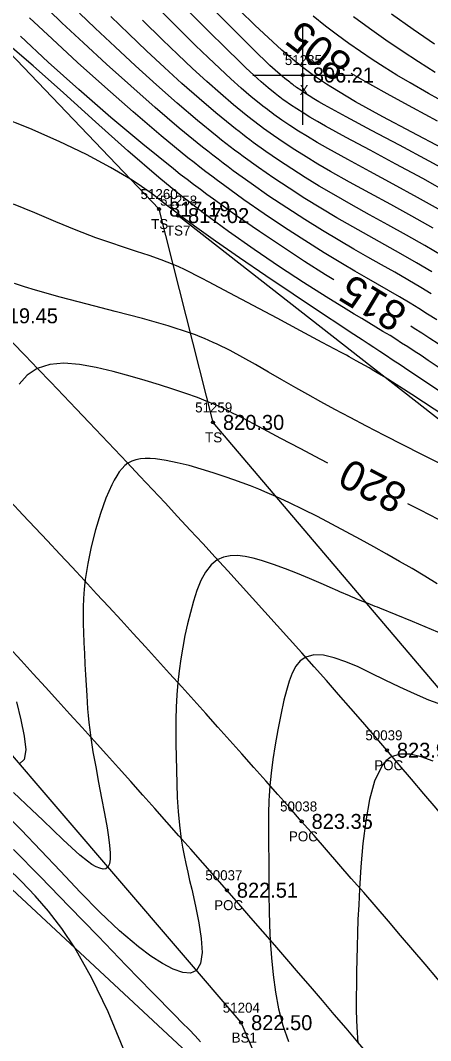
# Model space of a CAD drawing. Extents: x 1378535 to 1380697, y 997729 to 1000024.
# Drawn here: x 1380282.6 to 1380323.7, y 998356.1 to 998458.3 of the extents above; entities that cross this region are included whole.
import ezdxf

# ---------------------------------------------------------------- set-up
doc = ezdxf.new("R2010")
doc.units = 0
for name, color, linetype in [('RD_DTM_BkLn1', 7, 'Continuous'), ('RD_DTM_BkLn2', 7, 'Continuous'), ('RD_DTM_BkLn_txCode', 7, 'Continuous'), ('RD_DTM_Major1', 7, 'Continuous'), ('RD_DTM_Major1_Lbl', 7, 'Continuous'), ('RD_DTM_Minor1', 7, 'Continuous'), ('RD_EX_Misc', 7, 'Continuous'), ('RD_EX_Misc_txCode', 7, 'Continuous'), ('RD_EX_Road', 7, 'Continuous'), ('RD_EX_Road_txCode', 7, 'Continuous'), ('RD_EX_TX_Misc_ELEV', 7, 'Continuous'), ('RD_EX_TX_Road_ELEV', 7, 'Continuous'), ('RD_HC_Survey_ELEV', 7, 'Continuous'), ('RD_HC_Survey_txCode', 7, 'Continuous'), ('RD_SMD_Locator', 7, 'Continuous')]:
    doc.layers.add(name, color=color, linetype=linetype)

msp = doc.modelspace()

# ---------------------------------------------------------------- linework, layer by layer
at = {"layer": 'RD_DTM_BkLn1'}
msp.add_spline([(1380561.34, 997899.22), (1380543.7, 997960.78), (1380525.01, 998016.6), (1380501.32, 998075.31), (1380476.75, 998129.12), (1380448.82, 998181.2), (1380418.35, 998233.12), (1380383.22, 998285.15), (1380349.47, 998331.42), (1380310.82, 998378.03), (1380271.62, 998420.47), (1380231.53, 998459.85)], degree=3, dxfattribs=at)
at = {"layer": 'RD_DTM_BkLn2'}
for p, q in [((1380341.21, 998405.27), (1380298.43, 998438.72)), ((1380300.33, 998353.98), (1380252.92, 998398.07))]:
    msp.add_line(p, q, dxfattribs=at)
for points in [[(1380321.82, 998326.62), (1380322.66, 998329.17), (1380322.26, 998332.77), (1380321.14, 998334.34), (1380320.11, 998334.64), (1380319.18, 998334.52), (1380315.04, 998338.98), (1380309.47, 998346.95), (1380304.76, 998357.87), (1380262.27, 998407.43), (1380207.07, 998458.85), (1380160.07, 998502.83), (1380114.55, 998544.04), (1380071.67, 998582.11), (1380029.13, 998620.78), (1379985.01, 998662.48), (1379936.38, 998704.35), (1379893.88, 998744.8), (1379846.87, 998787.95), (1379800.33, 998830.07), (1379753.88, 998865.5), (1379725.58, 998874.5)], [(1380445.27, 998223.72), (1380425.52, 998250), (1380406.53, 998278.61), (1380381.95, 998317.02), (1380359.79, 998349.51), (1380336.16, 998377.73), (1380301.94, 998418), (1380296.54, 998439.37), (1380254.32, 998483.53), (1380245.59, 998494.96), (1380223.31, 998517.04), (1380192.01, 998537.14)]]:
    msp.add_lwpolyline(points, dxfattribs=at)
at = {"layer": 'RD_DTM_Major1'}
for points in [[(1380324, 998437.47), (1380321.88, 998438.65), (1380319.75, 998439.82), (1380317.65, 998440.97), (1380315.63, 998442.08), (1380313.73, 998443.14), (1380312.46, 998443.88), (1380311.27, 998444.6), (1380310.14, 998445.31), (1380309.06, 998446.02), (1380308.01, 998446.73), (1380307, 998447.45), (1380306.71, 998447.67), (1380306.43, 998447.88), (1380306.14, 998448.1), (1380305.85, 998448.32), (1380305.56, 998448.55), (1380305.27, 998448.78), (1380304.01, 998449.81), (1380302.69, 998450.94), (1380301.32, 998452.15), (1380299.89, 998453.46), (1380298.41, 998454.85), (1380296.87, 998456.33), (1380294.86, 998458.29)], [(1380314.05, 998432.29), (1380313.21, 998432.8), (1380311.11, 998434.13), (1380308.9, 998435.58), (1380306.61, 998437.11), (1380304.29, 998438.71), (1380301.98, 998440.36), (1380301.32, 998440.84), (1380300.67, 998441.33), (1380300, 998441.82), (1380299.34, 998442.33), (1380298.66, 998442.85), (1380297.98, 998443.39), (1380294.91, 998445.86), (1380291.71, 998448.56), (1380288.5, 998451.35), (1380285.43, 998454.1), (1380282.63, 998456.68)], [(1380324.44, 998448.17), (1380321.98, 998449.5), (1380319.7, 998450.74), (1380317.65, 998451.88), (1380316.73, 998452.42), (1380315.87, 998452.93), (1380315.78, 998452.98)], [(1380324.51, 998425.86), (1380323.66, 998426.41), (1380322.87, 998426.93), (1380322.11, 998427.42), (1380321.75, 998427.64)], [(1380313.44, 998413.92), (1380312.75, 998414.27), (1380310.66, 998415.37), (1380308.73, 998416.39), (1380307, 998417.31), (1380305.49, 998418.11), (1380304.93, 998418.41), (1380304.4, 998418.68), (1380303.9, 998418.94), (1380303.41, 998419.18), (1380302.92, 998419.42), (1380302.43, 998419.65), (1380302.27, 998419.72), (1380302.1, 998419.79), (1380301.94, 998419.86), (1380301.77, 998419.93), (1380301.59, 998420), (1380301.42, 998420.07), (1380300.37, 998420.48), (1380299.2, 998420.89), (1380297.93, 998421.32), (1380296.57, 998421.76), (1380295.13, 998422.19), (1380293.65, 998422.63), (1380291.94, 998423.1), (1380290.23, 998423.51), (1380288.57, 998423.8), (1380287, 998423.92), (1380285.57, 998423.81), (1380284.31, 998423.41), (1380283.32, 998422.74), (1380282.51, 998421.83)], [(1380325.43, 998407.82), (1380322.73, 998409.2), (1380321.46, 998409.84)], [(1380282.23, 998390), (1380282.69, 998388.21), (1380283.03, 998386.57), (1380283.17, 998385.21), (1380283.03, 998384.24), (1380282.54, 998383.79)]]:
    msp.add_lwpolyline(points, dxfattribs=at)
at = {"layer": 'RD_DTM_Minor1'}
for points in [[(1380324.92, 998445.48), (1380321.88, 998447.07), (1380318.95, 998448.62), (1380316.21, 998450.13), (1380313.76, 998451.6), (1380313.33, 998451.87), (1380312.92, 998452.14), (1380312.52, 998452.41), (1380312.12, 998452.68), (1380311.73, 998452.96), (1380311.35, 998453.24), (1380310.94, 998453.56), (1380310.53, 998453.88), (1380310.11, 998454.21), (1380309.7, 998454.56), (1380309.27, 998454.92), (1380308.84, 998455.29), (1380306.14, 998457.8), (1380303.13, 998460.75)], [(1380324.85, 998439.19), (1380322.43, 998440.54), (1380320.01, 998441.86), (1380317.67, 998443.12), (1380315.45, 998444.33), (1380313.44, 998445.44), (1380312.39, 998446.05), (1380311.41, 998446.63), (1380310.5, 998447.19), (1380309.65, 998447.74), (1380308.83, 998448.29), (1380308.05, 998448.85), (1380307.83, 998449.01), (1380307.61, 998449.17), (1380307.39, 998449.34), (1380307.17, 998449.51), (1380306.94, 998449.68), (1380306.72, 998449.85), (1380305.76, 998450.63), (1380304.77, 998451.49), (1380303.73, 998452.42), (1380302.63, 998453.44), (1380301.46, 998454.55), (1380300.2, 998455.76), (1380298.06, 998457.88), (1380295.74, 998460.19)], [(1380325.69, 998440.91), (1380322.97, 998442.42), (1380320.27, 998443.88), (1380317.69, 998445.26), (1380315.3, 998446.54), (1380313.21, 998447.69), (1380312.4, 998448.15), (1380311.66, 998448.58), (1380310.97, 998449), (1380310.33, 998449.41), (1380309.72, 998449.81), (1380309.14, 998450.21), (1380308.98, 998450.33), (1380308.81, 998450.45), (1380308.65, 998450.57), (1380308.49, 998450.69), (1380308.33, 998450.82), (1380308.17, 998450.94), (1380307.48, 998451.5), (1380306.77, 998452.11), (1380306.03, 998452.78), (1380305.24, 998453.52), (1380304.38, 998454.34), (1380303.45, 998455.25), (1380301.23, 998457.46), (1380298.69, 998460.01)], [(1380326.61, 998442.54), (1380323.61, 998444.18), (1380320.64, 998445.76), (1380317.83, 998447.25), (1380315.27, 998448.61), (1380313.09, 998449.82), (1380312.56, 998450.13), (1380312.06, 998450.42), (1380311.59, 998450.71), (1380311.15, 998450.99), (1380310.73, 998451.27), (1380310.32, 998451.56), (1380310.2, 998451.64), (1380310.09, 998451.72), (1380309.97, 998451.81), (1380309.86, 998451.89), (1380309.75, 998451.98), (1380309.63, 998452.07), (1380309.15, 998452.45), (1380308.67, 998452.86), (1380308.17, 998453.3), (1380307.64, 998453.77), (1380307.09, 998454.29), (1380306.5, 998454.86), (1380304.18, 998457.15), (1380301.45, 998459.91)], [(1380323.82, 998430.89), (1380322.78, 998431.52), (1380321.48, 998432.28), (1380320.16, 998433.04), (1380318.81, 998433.8), (1380317.45, 998434.57), (1380316.06, 998435.36), (1380314.65, 998436.18), (1380312.91, 998437.22), (1380311.13, 998438.33), (1380309.34, 998439.48), (1380307.54, 998440.68), (1380305.75, 998441.93), (1380303.97, 998443.21), (1380303.47, 998443.59), (1380302.96, 998443.97), (1380302.45, 998444.36), (1380301.93, 998444.76), (1380301.42, 998445.16), (1380300.89, 998445.58), (1380298.56, 998447.48), (1380296.14, 998449.55), (1380293.69, 998451.71), (1380291.27, 998453.89), (1380288.95, 998456.02), (1380286.79, 998458.04), (1380285.51, 998459.26)], [(1380323.87, 998433.1), (1380322.32, 998434), (1380320.75, 998434.89), (1380319.15, 998435.78), (1380317.55, 998436.68), (1380315.95, 998437.58), (1380314.35, 998438.5), (1380312.74, 998439.46), (1380311.15, 998440.44), (1380309.57, 998441.45), (1380308.02, 998442.48), (1380306.49, 998443.54), (1380304.97, 998444.64), (1380304.54, 998444.96), (1380304.11, 998445.28), (1380303.67, 998445.61), (1380303.24, 998445.95), (1380302.8, 998446.29), (1380302.35, 998446.64), (1380300.4, 998448.24), (1380298.36, 998449.98), (1380296.28, 998451.81), (1380294.18, 998453.71), (1380292.12, 998455.62), (1380290.12, 998457.5), (1380288.56, 998459)], [(1380324.97, 998434.67), (1380323.16, 998435.72), (1380321.32, 998436.76), (1380319.46, 998437.79), (1380317.61, 998438.81), (1380315.8, 998439.82), (1380314.04, 998440.82), (1380312.59, 998441.68), (1380311.19, 998442.53), (1380309.83, 998443.39), (1380308.52, 998444.26), (1380307.24, 998445.15), (1380305.98, 998446.05), (1380305.62, 998446.32), (1380305.26, 998446.59), (1380304.91, 998446.86), (1380304.55, 998447.14), (1380304.18, 998447.42), (1380303.82, 998447.71), (1380302.21, 998449.02), (1380300.55, 998450.44), (1380298.83, 998451.96), (1380297.07, 998453.56), (1380295.29, 998455.22), (1380293.49, 998456.92), (1380291.69, 998458.67)], [(1380325.46, 998449.87), (1380323.53, 998450.96), (1380321.7, 998452.01), (1380320.38, 998452.8), (1380319.11, 998453.58), (1380317.89, 998454.36), (1380316.71, 998455.15), (1380315.56, 998455.95), (1380314.42, 998456.78), (1380313.21, 998457.71), (1380311.99, 998458.68)], [(1380324.19, 998453.06), (1380322.54, 998454.11), (1380320.9, 998455.19), (1380319.27, 998456.3), (1380317.64, 998457.45), (1380316.01, 998458.64)], [(1380324.13, 998455.9), (1380322, 998457.37), (1380319.84, 998458.91)], [(1380324.36, 998428.28), (1380323.45, 998428.85), (1380322.58, 998429.4), (1380321.71, 998429.93), (1380320.63, 998430.57), (1380319.54, 998431.2), (1380318.44, 998431.84), (1380317.31, 998432.48), (1380316.14, 998433.16), (1380314.93, 998433.87), (1380313.07, 998435), (1380311.13, 998436.21), (1380309.12, 998437.51), (1380307.08, 998438.88), (1380305.02, 998440.31), (1380302.98, 998441.79), (1380302.39, 998442.22), (1380301.81, 998442.66), (1380301.22, 998443.11), (1380300.63, 998443.56), (1380300.04, 998444.03), (1380299.43, 998444.51), (1380296.74, 998446.72), (1380293.93, 998449.12), (1380291.11, 998451.6), (1380288.37, 998454.07), (1380285.81, 998456.41), (1380283.54, 998458.52)], [(1380326.22, 998422.4), (1380323.52, 998424.21), (1380322.79, 998424.69), (1380322.1, 998425.14), (1380321.46, 998425.56), (1380320.84, 998425.95), (1380320.25, 998426.33), (1380319.68, 998426.69), (1380318.97, 998427.12), (1380318.27, 998427.55), (1380317.57, 998427.97), (1380316.85, 998428.41), (1380316.09, 998428.86), (1380315.3, 998429.34), (1380313.27, 998430.59), (1380311.02, 998432.02), (1380308.6, 998433.6), (1380306.07, 998435.31), (1380303.5, 998437.12), (1380300.94, 998439.01), (1380300.21, 998439.56), (1380299.48, 998440.12), (1380298.75, 998440.7), (1380298.02, 998441.29), (1380297.27, 998441.9), (1380296.51, 998442.53), (1380293.41, 998445.21), (1380290.17, 998448.1), (1380286.95, 998451), (1380283.9, 998453.73), (1380281.15, 998456.08)], [(1380324.65, 998421.12), (1380321.68, 998423.1), (1380321.14, 998423.47), (1380320.61, 998423.82), (1380320.1, 998424.15), (1380319.13, 998424.8), (1380318.65, 998425.11), (1380318.06, 998425.49), (1380317.48, 998425.87), (1380316.89, 998426.26), (1380315.68, 998427.05), (1380315.04, 998427.47), (1380312.61, 998429.08), (1380309.97, 998430.84), (1380307.25, 998432.68), (1380304.61, 998434.48), (1380302.18, 998436.17), (1380300.09, 998437.66), (1380299.57, 998438.03), (1380299.08, 998438.39), (1380298.63, 998438.73), (1380298.2, 998439.05), (1380297.8, 998439.36), (1380297.41, 998439.66), (1380296.86, 998440.09), (1380296.3, 998440.52), (1380295.74, 998440.96), (1380295.12, 998441.4), (1380294.44, 998441.87), (1380293.67, 998442.37), (1380291.67, 998443.54), (1380289.26, 998444.83), (1380286.53, 998446.15), (1380283.58, 998447.45), (1380280.52, 998448.65)], [(1380325.26, 998418.55), (1380321.85, 998420.8), (1380319.11, 998422.55), (1380318.56, 998422.88), (1380318.06, 998423.18), (1380317.59, 998423.46), (1380317.15, 998423.71), (1380316.73, 998423.95), (1380316.3, 998424.18), (1380316.06, 998424.31), (1380315.57, 998424.58), (1380315.31, 998424.72), (1380315.05, 998424.86), (1380314.78, 998425.01), (1380312.88, 998426.02), (1380310.7, 998427.19), (1380308.36, 998428.44), (1380305.96, 998429.71), (1380303.64, 998430.95), (1380301.49, 998432.08), (1380300.86, 998432.41), (1380300.26, 998432.73), (1380299.67, 998433.02), (1380299.09, 998433.31), (1380298.52, 998433.57), (1380297.94, 998433.83), (1380296.76, 998434.29), (1380295.54, 998434.72), (1380294.28, 998435.13), (1380292.96, 998435.55), (1380291.6, 998436.01), (1380290.19, 998436.5), (1380288.23, 998437.27), (1380286.19, 998438.1), (1380284.09, 998438.98), (1380281.93, 998439.85)], [(1380326.9, 998412.77), (1380322.86, 998414.8), (1380319.14, 998416.7), (1380317.32, 998417.64), (1380315.67, 998418.5), (1380314.16, 998419.31), (1380312.76, 998420.06), (1380311.46, 998420.78), (1380310.24, 998421.47), (1380308.84, 998422.27), (1380307.49, 998423.05), (1380306.19, 998423.8), (1380304.92, 998424.51), (1380303.65, 998425.19), (1380302.36, 998425.83), (1380301.95, 998426.02), (1380301.53, 998426.21), (1380301.1, 998426.4), (1380300.65, 998426.58), (1380300.17, 998426.77), (1380299.68, 998426.95), (1380297.45, 998427.67), (1380294.89, 998428.4), (1380292.14, 998429.12), (1380289.34, 998429.84), (1380286.63, 998430.55), (1380284.15, 998431.25), (1380283.05, 998431.58), (1380282.03, 998431.91)], [(1380324.4, 998401.84), (1380323.16, 998402.6), (1380321.91, 998403.35), (1380320.64, 998404.08), (1380319.35, 998404.81), (1380318.05, 998405.54), (1380316.72, 998406.27), (1380315.29, 998407.04), (1380313.84, 998407.81), (1380312.41, 998408.56), (1380310.99, 998409.28), (1380309.6, 998409.95), (1380308.25, 998410.57), (1380307.38, 998410.95), (1380306.53, 998411.3), (1380305.69, 998411.64), (1380304.86, 998411.95), (1380304.02, 998412.26), (1380303.17, 998412.55), (1380301.97, 998412.95), (1380300.75, 998413.33), (1380299.54, 998413.67), (1380298.36, 998413.96), (1380297.23, 998414.19), (1380296.17, 998414.34), (1380295.64, 998414.38), (1380295.14, 998414.38), (1380294.67, 998414.35), (1380294.22, 998414.26), (1380293.81, 998414.12), (1380293.42, 998413.91), (1380293.11, 998413.67), (1380292.83, 998413.38), (1380292.55, 998413.04), (1380292.29, 998412.66), (1380292.04, 998412.23), (1380291.8, 998411.75), (1380291.21, 998410.41), (1380290.66, 998408.88), (1380290.16, 998407.24), (1380289.73, 998405.54), (1380289.38, 998403.86), (1380289.13, 998402.26), (1380289.02, 998401.28), (1380288.96, 998400.36), (1380288.93, 998399.48), (1380288.92, 998398.63), (1380288.94, 998397.8), (1380288.97, 998396.98), (1380289.01, 998395.92), (1380289.05, 998394.85), (1380289.11, 998393.79), (1380289.16, 998392.73), (1380289.22, 998391.68), (1380289.28, 998390.64), (1380289.33, 998389.98), (1380289.37, 998389.32), (1380289.43, 998388.64), (1380289.5, 998387.93), (1380289.58, 998387.19), (1380289.69, 998386.4), (1380289.91, 998385), (1380290.18, 998383.5), (1380290.47, 998381.94), (1380290.78, 998380.37), (1380291.07, 998378.83), (1380291.33, 998377.39), (1380291.47, 998376.46), (1380291.58, 998375.62), (1380291.64, 998374.88), (1380291.64, 998374.26), (1380291.57, 998373.77), (1380291.41, 998373.44), (1380291.2, 998373.29), (1380290.93, 998373.26), (1380290.61, 998373.33), (1380290.23, 998373.49), (1380289.81, 998373.73), (1380289.35, 998374.05), (1380288.6, 998374.65), (1380287.78, 998375.37), (1380286.89, 998376.21), (1380285.93, 998377.14), (1380284.89, 998378.14), (1380283.79, 998379.2), (1380281.94, 998380.94)], [(1380325.73, 998396.44), (1380321.93, 998398.04), (1380318.66, 998399.38), (1380318.42, 998399.48), (1380318.18, 998399.57), (1380317.95, 998399.67), (1380317.72, 998399.76), (1380317.5, 998399.85), (1380317.29, 998399.93), (1380316.97, 998400.06), (1380316.37, 998400.31), (1380316.09, 998400.43), (1380315.82, 998400.54), (1380315.55, 998400.65), (1380315.27, 998400.77), (1380315, 998400.89), (1380314.73, 998401.01), (1380314.46, 998401.12), (1380314.2, 998401.24), (1380313.93, 998401.36), (1380312.79, 998401.86), (1380311.62, 998402.36), (1380310.42, 998402.86), (1380309.22, 998403.34), (1380308.01, 998403.78), (1380306.81, 998404.17), (1380305.98, 998404.39), (1380305.17, 998404.56), (1380304.39, 998404.66), (1380303.66, 998404.65), (1380302.98, 998404.51), (1380302.36, 998404.24), (1380301.74, 998403.72), (1380301.2, 998403.01), (1380300.73, 998402.15), (1380300.33, 998401.16), (1380299.98, 998400.08), (1380299.67, 998398.95), (1380299.39, 998397.81), (1380299.13, 998396.65), (1380298.9, 998395.48), (1380298.7, 998394.31), (1380298.54, 998393.13), (1380298.41, 998391.96), (1380298.32, 998390.71), (1380298.26, 998389.48), (1380298.23, 998388.24), (1380298.22, 998387.01), (1380298.23, 998385.77), (1380298.25, 998384.52), (1380298.27, 998383.16), (1380298.3, 998381.78), (1380298.36, 998380.41), (1380298.44, 998379.02), (1380298.57, 998377.64), (1380298.75, 998376.26), (1380298.89, 998375.44), (1380299.05, 998374.63), (1380299.22, 998373.8), (1380299.41, 998372.96), (1380299.6, 998372.11), (1380299.81, 998371.23), (1380300.19, 998369.55), (1380300.52, 998367.87), (1380300.76, 998366.29), (1380300.84, 998364.9), (1380300.7, 998363.8), (1380300.28, 998363.09), (1380299.7, 998362.84), (1380298.91, 998362.9), (1380297.96, 998363.22), (1380296.88, 998363.78), (1380295.71, 998364.53), (1380294.48, 998365.45), (1380292.56, 998367.08), (1380290.61, 998368.93), (1380288.64, 998370.94), (1380286.65, 998373.03), (1380284.68, 998375.13), (1380282.72, 998377.17), (1380281.09, 998378.81)], [(1380324.97, 998389.67), (1380323.56, 998390.19), (1380322.12, 998390.8), (1380320.67, 998391.48), (1380319.21, 998392.19), (1380317.77, 998392.89), (1380316.48, 998393.5), (1380315.25, 998394.02), (1380314.08, 998394.43), (1380313, 998394.68), (1380312.04, 998394.71), (1380311.23, 998394.5), (1380310.69, 998394.13), (1380310.25, 998393.58), (1380309.87, 998392.89), (1380309.56, 998392.08), (1380309.29, 998391.16), (1380309.04, 998390.17), (1380308.73, 998388.72), (1380308.44, 998387.22), (1380308.18, 998385.71), (1380307.95, 998384.24), (1380307.77, 998382.85), (1380307.64, 998381.6), (1380307.59, 998381.08), (1380307.56, 998380.59), (1380307.53, 998380.12), (1380307.52, 998379.68), (1380307.5, 998379.25), (1380307.5, 998378.82), (1380307.49, 998378.15), (1380307.49, 998377.48), (1380307.5, 998376.78), (1380307.51, 998376.06), (1380307.51, 998375.31), (1380307.52, 998374.51), (1380307.52, 998373.29), (1380307.53, 998371.98), (1380307.54, 998370.6), (1380307.57, 998369.14), (1380307.61, 998367.62), (1380307.68, 998366.06), (1380307.79, 998364.37), (1380307.96, 998362.66), (1380308.19, 998360.94), (1380308.52, 998359.25), (1380308.95, 998357.59), (1380309.51, 998355.98)], [(1380324, 998384.06), (1380322.8, 998384.49), (1380321.7, 998384.75), (1380320.72, 998384.78), (1380319.88, 998384.54), (1380319.68, 998384.42), (1380319.49, 998384.28), (1380319.3, 998384.12), (1380319.13, 998383.93), (1380318.97, 998383.73), (1380318.82, 998383.5), (1380318.14, 998382.06), (1380317.62, 998380.21), (1380317.24, 998378.09), (1380316.96, 998375.81), (1380316.76, 998373.49), (1380316.62, 998371.27), (1380316.54, 998369.69), (1380316.47, 998368.21), (1380316.42, 998366.82), (1380316.38, 998365.49), (1380316.35, 998364.21), (1380316.33, 998362.95), (1380316.31, 998361.69), (1380316.3, 998360.44), (1380316.3, 998359.23), (1380316.33, 998358.04), (1380316.38, 998356.9), (1380316.47, 998355.81)], [(1380300.69, 998355.95), (1380300.15, 998356.54), (1380299.54, 998357.18), (1380298.85, 998357.86), (1380298.1, 998358.62), (1380295.85, 998360.91), (1380293.25, 998363.6), (1380290.44, 998366.52), (1380287.54, 998369.52), (1380284.66, 998372.47), (1380281.94, 998375.21)], [(1380292.95, 998355.31), (1380291.44, 998358.94), (1380289.8, 998362.33), (1380288.09, 998365.36), (1380286.79, 998367.31), (1380285.46, 998369.04), (1380284.12, 998370.59), (1380282.75, 998372.02), (1380281.36, 998373.37)]]:
    msp.add_lwpolyline(points, dxfattribs=at)
at = {"layer": 'RD_EX_Misc'}
for p, q in [((1380310.94, 998447.8), (1380310.94, 998457.8)), ((1380305.94, 998452.8), (1380315.94, 998452.8))]:
    msp.add_line(p, q, dxfattribs=at)
at = {"layer": 'RD_EX_Road'}
for points in [[(1380571.28, 997900.85), (1380553.84, 997963.23), (1380535.07, 998018.79), (1380510.81, 998079.18), (1380486.36, 998133.16), (1380458.39, 998185.94), (1380428.11, 998238.22), (1380392.69, 998291.14), (1380357.52, 998337.62), (1380319.37, 998385.16), (1380279.26, 998428.68), (1380239.6, 998468.13), (1380183.37, 998518.83)], [(1380551.89, 997897.33), (1380534.24, 997958.2), (1380514.83, 998013.47), (1380491.08, 998070.75), (1380467.52, 998124.4), (1380439.88, 998176.53), (1380409.17, 998228.12), (1380375.89, 998278.45), (1380340.75, 998326.22), (1380303.33, 998371.14), (1380263.98, 998413.97), (1380224.66, 998452.64), (1380168.71, 998504.79)]]:
    msp.add_spline(points, degree=3, dxfattribs=at)
at = {"layer": 'RD_SMD_Locator'}
for centre in [(1380309.18, 998454.94), (1380310.94, 998452.8), (1380296.54, 998439.37), (1380298.43, 998438.72), (1380301.94, 998418), (1380319.37, 998385.16), (1380310.82, 998378.03), (1380303.33, 998371.14), (1380304.76, 998357.87)]:
    msp.add_circle(centre, 0.15, dxfattribs=at)

# ---------------------------------------------------------------- texts
at = {"layer": 'RD_DTM_BkLn_txCode'}
for s, p in [('51260', (1380294.68, 998440.37)), ('51258', (1380296.63, 998439.72)), ('TS', (1380295.74, 998437.37)), ('-TS7', (1380296.78, 998436.72)), ('51259', (1380300.15, 998419)), ('TS', (1380301.15, 998416)), ('51204', (1380302.92, 998358.87)), ('BS1', (1380303.81, 998355.87))]:
    msp.add_text(s, height=1, dxfattribs=at).set_placement(p)
at = {"layer": 'RD_DTM_Major1_Lbl'}
for s, rotation, p in [('805', 142.1817, (1380316.08, 998454.34)), ('815', 148.9149, (1380321.59, 998429.5)), ('820', 153.0556, (1380321.59, 998411.44))]:
    msp.add_text(s, height=3, rotation=rotation, dxfattribs=at).set_placement(p)
at = {"layer": 'RD_EX_Misc_txCode'}
for s, p in [('51285', (1380309.14, 998453.8)), ('X', (1380310.62, 998450.8))]:
    msp.add_text(s, height=1, dxfattribs=at).set_placement(p)
at = {"layer": 'RD_EX_Road_txCode'}
for s, p in [('50039', (1380317.21, 998386.16)), ('POC', (1380318.1, 998383.16)), ('50037', (1380301.17, 998372.14)), ('POC', (1380302.06, 998369.14))]:
    msp.add_text(s, height=1, dxfattribs=at).set_placement(p)
at = {"layer": 'RD_EX_TX_Misc_ELEV'}
for s, p in [('806.21', (1380311.94, 998452.05)), ('817.19', (1380297.54, 998438.62)), ('817.02', (1380299.43, 998437.97)), ('820.30', (1380302.94, 998417.25)), ('822.50', (1380305.76, 998357.12))]:
    msp.add_text(s, height=1.5, dxfattribs=at).set_placement(p)
at = {"layer": 'RD_EX_TX_Road_ELEV'}
for s, p in [('819.45', (1380280.26, 998427.93)), ('823.94', (1380320.37, 998384.41)), ('822.51', (1380304.33, 998370.39))]:
    msp.add_text(s, height=1.5, dxfattribs=at).set_placement(p)
at = {"layer": 'RD_HC_Survey_ELEV'}
msp.add_text('823.35', height=1.5, dxfattribs=at).set_placement((1380311.82, 998377.28))
at = {"layer": 'RD_HC_Survey_txCode'}
for s, p in [('50038', (1380308.66, 998379.03)), ('POC', (1380309.55, 998376.03))]:
    msp.add_text(s, height=1, dxfattribs=at).set_placement(p)

doc.saveas('drawing.dxf')
